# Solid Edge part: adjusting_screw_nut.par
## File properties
Title: Adjusting screw nut
Author: Abhinav Rai
Template: Normal.par
Last saved by: Cadcim
Revision: 7
Application: Solid Edge
Material: aluminum
Accuracy: 0.99
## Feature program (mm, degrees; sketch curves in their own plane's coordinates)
sketch for "unnamed RevolvedProtrusion 1" plane through (0, 0, 0) normal (0, -1, 0) x-axis (1, 0, 0)
  line (25.4, 9.7462) -> (74.676, 9.7462)
  line (76.2, 8.2222) -> (74.676, 9.7462)
  line (76.2, -26.8298) -> (76.2, 8.2222)
  line (76.2, -26.8298) -> (74.676, -28.3538)
  line (74.676, -28.3538) -> (47.625, -28.3538)
  line (47.625, -28.3538) -> (47.625, -60.1038)
  line (47.625, -60.1038) -> (25.4, -60.1038)
  line (25.4, -60.1038) -> (25.4, 9.7462)
revolve "unnamed RevolvedProtrusion 1" add full turn 360 deg
sketch for "Hole_1" plane through (76.2, 0, 0) normal (1, 0, 0) x-axis (0, 1, 0)
  hole centre (0, -9.3038) bore radius 9.5123
hole "Hole_1" diameter 19.0246 finite  VBottomAngle = 118 deg
pattern "unnamed Pattern 1" of "Hole_1"
pattern "unnamed Pattern 2"
sketch for "unnamed Cutout 1" plane through (0, 0, 9.7462) normal (0, 0, 1) x-axis (1, 0, 0)
extrude "unnamed Cutout 1" cut through along -normal
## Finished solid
Body 1: solid body, 16 faces, 16 edges, 4 vertices.
  Faces by surface: cylinder 7, cone 6, plane 3
  Edges by curve: circle 12, intersection 4
Bounding box of the edges (mm): 152.400 x 152.400 x 69.850, from (-76.2, -76.2, -60.1038) to (76.2, 76.2, 9.7462).
Cylindrical faces by radius (mm): R9.5123 x4, R38.1 x1, R47.625 x1, R76.2 x1
Conical faces (half-angle, radius in mm at the cone's reference point): 45 deg R74.676 x1, 45 deg R76.2 x1, 59 deg R9.5123 x4
Planar faces by outward normal: +z 1, -z 2
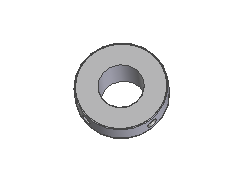
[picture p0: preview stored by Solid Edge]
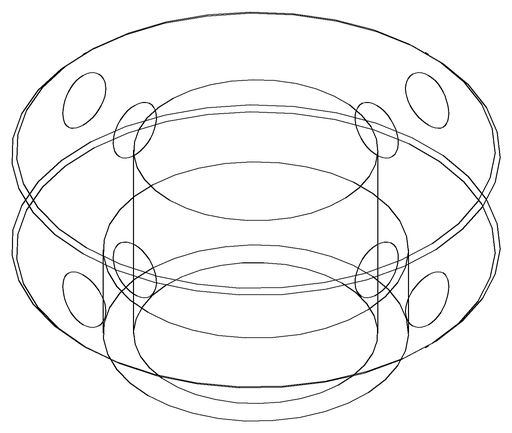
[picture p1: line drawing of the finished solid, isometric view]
